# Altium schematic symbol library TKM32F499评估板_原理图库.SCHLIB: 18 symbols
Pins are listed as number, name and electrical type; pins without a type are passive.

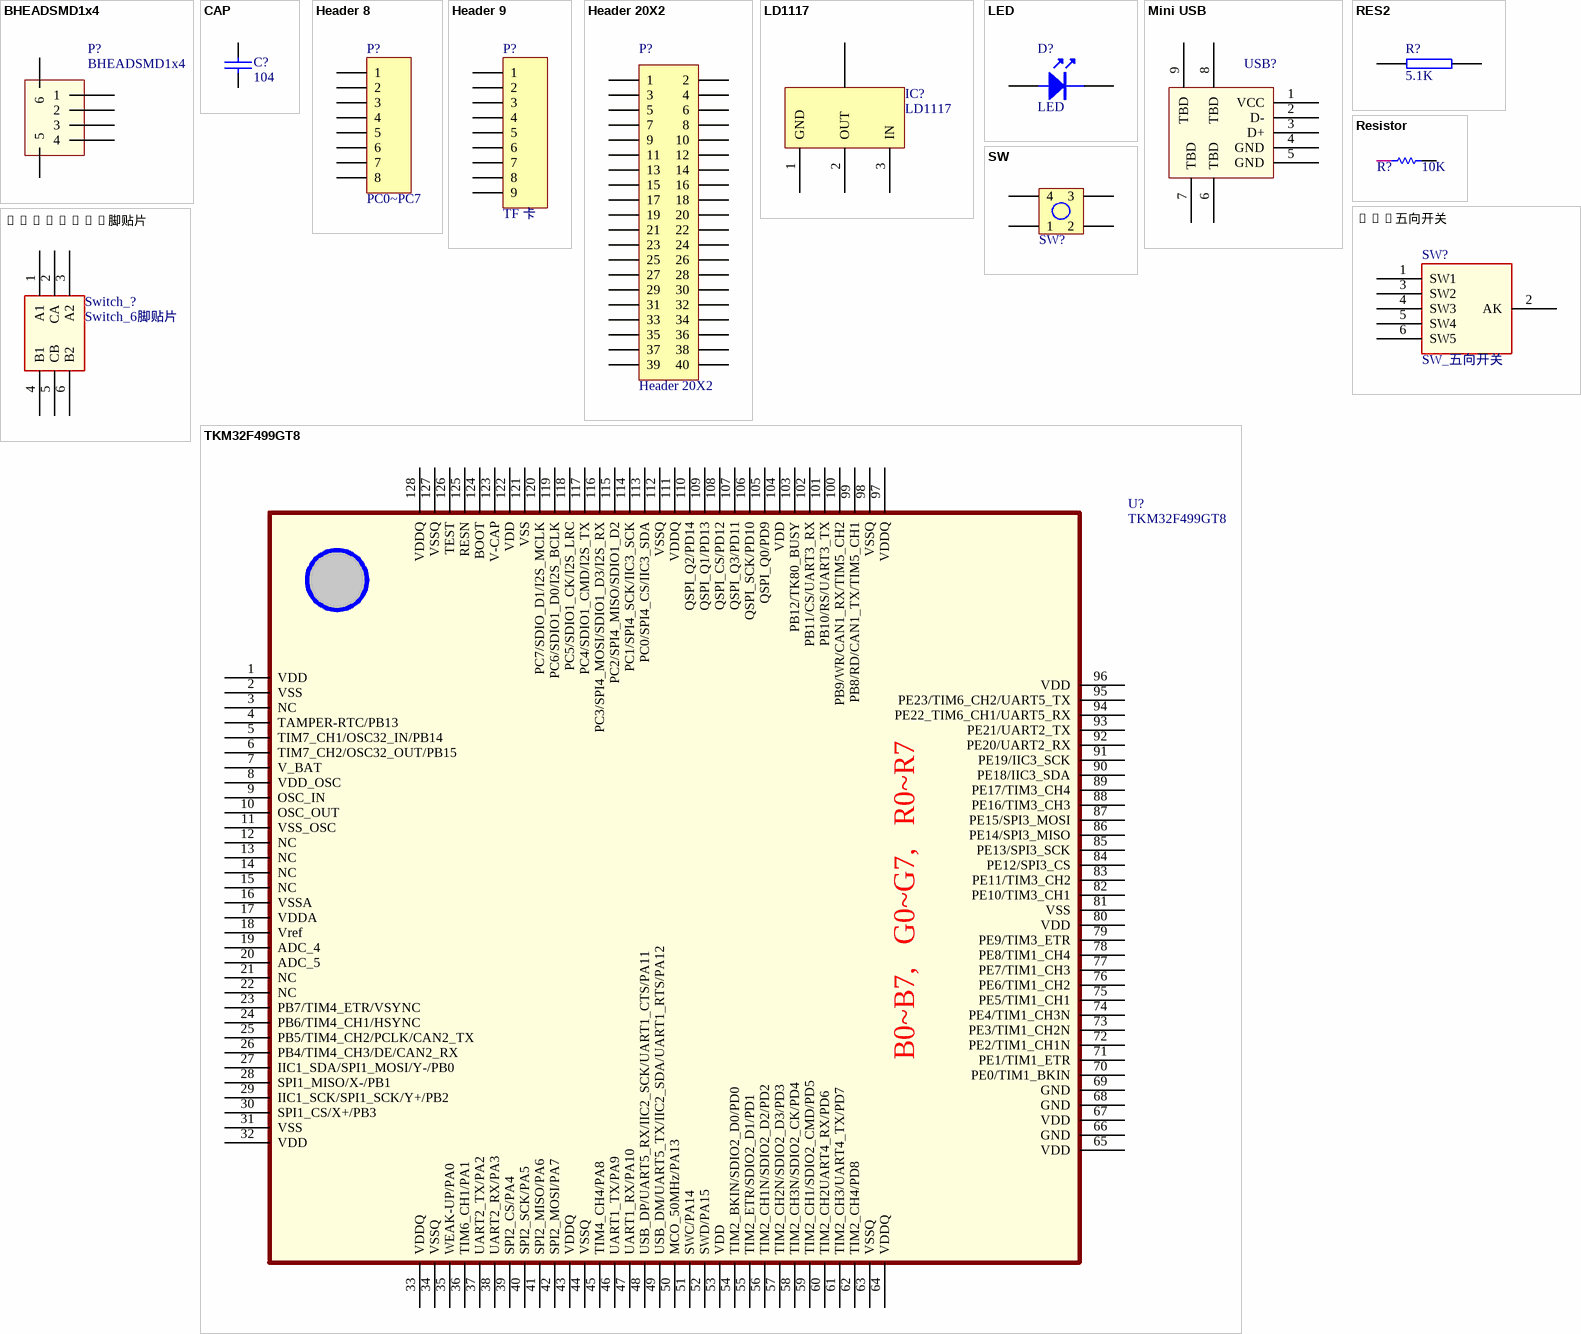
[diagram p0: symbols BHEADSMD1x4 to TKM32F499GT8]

## BHEADSMD1x4
designator P?
footprint BHEADSMD1x4
pins: 1, 2, 3, 4, 5, 6

## CAP
designator C?, comment 104
Capacitor
footprint C0805 (Chip Capacitor; Body 2.0 x 1.2 mm (LxW typ))
footprint R0805
footprint C0603
footprint C0402-1
pins: 1, 2
2 alternate drawings of the same symbol

## Header 8
designator P?, comment PC0~PC7
Header, 8-Pin
footprint HDR1X8 (Connector; Header; 8 Position)
signal-integrity model Connector
pins: 1, 2, 3, 4, 5, 6, 7, 8

## Header 9
designator P?, comment TF 卡
Header, 9-Pin
footprint HDR1X9 (Connector; Header; 9 Position)
signal-integrity model Connector
footprint Micro_SD
pins: 1, 2, 3, 4, 5, 6, 7, 8, 9

## Header 20X2
designator P?
Header, 20-Pin, Dual row
footprint P_Head_2x20
signal-integrity model Connector
pins: 1, 2, 3, 4, 5, 6, 7, 8, 9, 10, 11, 12, 13, 14, 15, 16, 17, 18, 19, 20, 21, 22, 23, 24, 25, 26, 27, 28, 29, 30, 31, 32, 33, 34, 35, 36, 37, 38, 39, 40

## LD1117
designator IC?
footprint SOT223
pins: 1 GND, 2 OUT, 2 OUT, 3 IN

## LED
designator D?
footprint D1206
footprint D0603
pins: 1, 2
2 alternate drawings of the same symbol

## Mini USB
designator USB?, comment Micro USB  (value not drawn)
footprint MicroUSB_带定位柱
pins: 1 VCC, 2 D-, 3 D+, 4 GND, 5 GND, 6 TBD, 7 TBD, 8 TBD, 9 TBD

## RES2
designator R?, comment 5.1K
footprint 0805
footprint R0805
footprint R0402
pins: 1, 2
2 alternate drawings of the same symbol

## Resistor
designator R?, comment 10K
footprint R0402
pins: 1, 2

## SW
designator SW?  (value not drawn)
footprint SW
pins: 1, 2, 3, 4

## SW_五向开关
designator SW?
footprint 五向开关
pins: 1 SW1, 2 AK, 3 SW2, 4 SW3, 5 SW4, 6 SW5

## Switch_6脚贴片
designator Switch_?
footprint Switch_6脚贴片
pins: 1 A1, 2 CA, 3 A2, 4 B1, 5 CB, 6 B2

## TKM32F499GT8
designator U?
footprint LQFP128
pins: 1 VDD, 2 VSS, 3 NC, 4 TAMPER-RTC/PB13, 5 TIM7_CH1/OSC32_IN/PB14, 6 TIM7_CH2/OSC32_OUT/PB15, 7 V_BAT, 8 VDD_OSC, 9 OSC_IN, 10 OSC_OUT, 11 VSS_OSC, 12 NC, 13 NC, 14 NC, 15 NC, 16 VSSA, 17 VDDA, 18 Vref, 19 ADC_4, 20 ADC_5, 21 NC, 22 NC, 23 PB7/TIM4_ETR/VSYNC, 24 PB6/TIM4_CH1/HSYNC, 25 PB5/TIM4_CH2/PCLK/CAN2_TX, 26 PB4/TIM4_CH3/DE/CAN2_RX, 27 IIC1_SDA/SPI1_MOSI/Y-/PB0, 28 SPI1_MISO/X-/PB1, 29 IIC1_SCK/SPI1_SCK/Y+/PB2, 30 SPI1_CS/X+/PB3, 31 VSS, 32 VDD, 33 VDDQ, 34 VSSQ, 35 WEAK-UP/PA0, 36 TIM6_CH1/PA1, 37 UART2_TX/PA2, 38 UART2_RX/PA3, 39 SPI2_CS/PA4, 40 SPI2_SCK/PA5, 41 SPI2_MISO/PA6, 42 SPI2_MOSI/PA7, 43 VDDQ, 44 VSSQ, 45 TIM4_CH4/PA8, 46 UART1_TX/PA9, 47 UART1_RX/PA10, 48 USB_DP/UART5_RX/IIC2_SCK/UART1_CTS/PA11, 49 USB_DM/UART5_TX/IIC2_SDA/UART1_RTS/PA12, 50 MCO_50MHz/PA13, 51 SWC/PA14, 52 SWD/PA15, 53 VDD, 54 TIM2_BKIN/SDIO2_D0/PD0, 55 TIM2_ETR/SDIO2_D1/PD1, 56 TIM2_CH1N/SDIO2_D2/PD2, 57 TIM2_CH2N/SDIO2_D3/PD3, 58 TIM2_CH3N/SDIO2_CK/PD4, 59 TIM2_CH1/SDIO2_CMD/PD5, 60 TIM2_CH2UART4_RX/PD6, 61 TIM2_CH3/UART4_TX/PD7, 62 TIM2_CH4/PD8, 63 VSSQ, 64 VDDQ, 65 VDD, 66 GND, 67 VDD, 68 GND, 69 GND, 70 PE0/TIM1_BKIN, 71 PE1/TIM1_ETR, 72 PE2/TIM1_CH1N, 73 PE3/TIM1_CH2N, 74 PE4/TIM1_CH3N, 75 PE5/TIM1_CH1, 76 PE6/TIM1_CH2, 77 PE7/TIM1_CH3, 78 PE8/TIM1_CH4, 79 PE9/TIM3_ETR, 80 VDD, 81 VSS, 82 PE10/TIM3_CH1, 83 PE11/TIM3_CH2, 84 PE12/SPI3_CS, 85 PE13/SPI3_SCK, 86 PE14/SPI3_MISO, 87 PE15/SPI3_MOSI, 88 PE16/TIM3_CH3, 89 PE17/TIM3_CH4, 90 PE18/IIC3_SDA, 91 PE19/IIC3_SCK, 92 PE20/UART2_RX, 93 PE21/UART2_TX, 94 PE22_TIM6_CH1/UART5_RX, 95 PE23/TIM6_CH2/UART5_TX, 96 VDD, 97 VDDQ, 98 VSSQ, 99 PB8/RD/CAN1_TX/TIM5_CH1, 100 PB9/WR/CAN1_RX/TIM5_CH2, 101 PB10/RS/UART3_TX, 102 PB11/CS/UART3_RX, 103 PB12/TK80_BUSY, 104 VDD, 105 QSPI_Q0/PD9, 106 QSPI_SCK/PD10, 107 QSPI_Q3/PD11, 108 QSPI_CS/PD12, 109 QSPI_Q1/PD13, 110 QSPI_Q2/PD14, 111 VDDQ, 112 VSSQ, 113 PC0/SPI4_CS/IIC3_SDA, 114 PC1/SPI4_SCK/IIC3_SCK, 115 PC2/SPI4_MISO/SDIO1_D2, 116 PC3/SPI4_MOSI/SDIO1_D3/I2S_RX, 117 PC4/SDIO1_CMD/I2S_TX, 118 PC5/SDIO1_CK/I2S_LRC, 119 PC6/SDIO1_D0/I2S_BCLK, 120 PC7/SDIO_D1/I2S_MCLK, 121 VSS, 122 VDD, 123 V-CAP, 124 BOOT, 125 RESN, 126 TEST, 127 VSSQ, 128 VDDQ

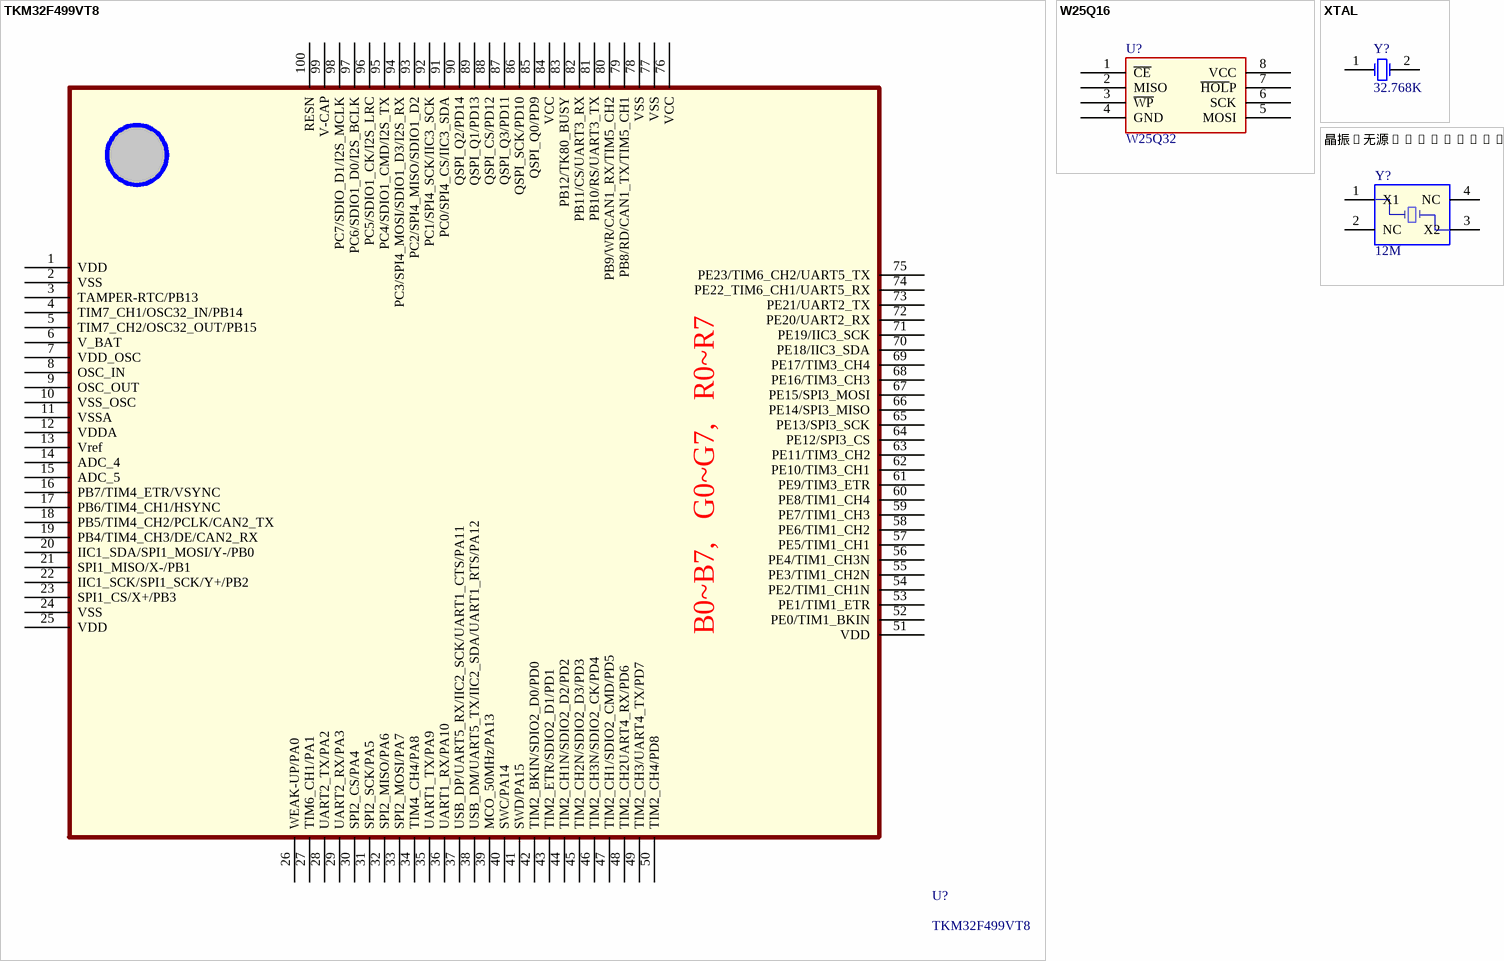
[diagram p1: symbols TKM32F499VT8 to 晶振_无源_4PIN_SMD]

## TKM32F499VT8
designator U?
footprint TQFP100
pins: 1 VDD, 2 VSS, 3 TAMPER-RTC/PB13, 4 TIM7_CH1/OSC32_IN/PB14, 5 TIM7_CH2/OSC32_OUT/PB15, 6 V_BAT, 7 VDD_OSC, 8 OSC_IN, 9 OSC_OUT, 10 VSS_OSC, 11 VSSA, 12 VDDA, 13 Vref, 14 ADC_4, 15 ADC_5, 16 PB7/TIM4_ETR/VSYNC, 17 PB6/TIM4_CH1/HSYNC, 18 PB5/TIM4_CH2/PCLK/CAN2_TX, 19 PB4/TIM4_CH3/DE/CAN2_RX, 20 IIC1_SDA/SPI1_MOSI/Y-/PB0, 21 SPI1_MISO/X-/PB1, 22 IIC1_SCK/SPI1_SCK/Y+/PB2, 23 SPI1_CS/X+/PB3, 24 VSS, 25 VDD, 26 WEAK-UP/PA0, 27 TIM6_CH1/PA1, 28 UART2_TX/PA2, 29 UART2_RX/PA3, 30 SPI2_CS/PA4, 31 SPI2_SCK/PA5, 32 SPI2_MISO/PA6, 33 SPI2_MOSI/PA7, 34 TIM4_CH4/PA8, 35 UART1_TX/PA9, 36 UART1_RX/PA10, 37 USB_DP/UART5_RX/IIC2_SCK/UART1_CTS/PA11, 38 USB_DM/UART5_TX/IIC2_SDA/UART1_RTS/PA12, 39 MCO_50MHz/PA13, 40 SWC/PA14, 41 SWD/PA15, 42 TIM2_BKIN/SDIO2_D0/PD0, 43 TIM2_ETR/SDIO2_D1/PD1, 44 TIM2_CH1N/SDIO2_D2/PD2, 45 TIM2_CH2N/SDIO2_D3/PD3, 46 TIM2_CH3N/SDIO2_CK/PD4, 47 TIM2_CH1/SDIO2_CMD/PD5, 48 TIM2_CH2UART4_RX/PD6, 49 TIM2_CH3/UART4_TX/PD7, 50 TIM2_CH4/PD8, 51 VDD, 52 PE0/TIM1_BKIN, 53 PE1/TIM1_ETR, 54 PE2/TIM1_CH1N, 55 PE3/TIM1_CH2N, 56 PE4/TIM1_CH3N, 57 PE5/TIM1_CH1, 58 PE6/TIM1_CH2, 59 PE7/TIM1_CH3, 60 PE8/TIM1_CH4, 61 PE9/TIM3_ETR, 62 PE10/TIM3_CH1, 63 PE11/TIM3_CH2, 64 PE12/SPI3_CS, 65 PE13/SPI3_SCK, 66 PE14/SPI3_MISO, 67 PE15/SPI3_MOSI, 68 PE16/TIM3_CH3, 69 PE17/TIM3_CH4, 70 PE18/IIC3_SDA, 71 PE19/IIC3_SCK, 72 PE20/UART2_RX, 73 PE21/UART2_TX, 74 PE22_TIM6_CH1/UART5_RX, 75 PE23/TIM6_CH2/UART5_TX, 76 VCC, 77 VSS, 78 VSS, 79 PB8/RD/CAN1_TX/TIM5_CH1, 80 PB9/WR/CAN1_RX/TIM5_CH2, 81 PB10/RS/UART3_TX, 82 PB11/CS/UART3_RX, 83 PB12/TK80_BUSY, 84 VCC, 85 QSPI_Q0/PD9, 86 QSPI_SCK/PD10, 87 QSPI_Q3/PD11, 88 QSPI_CS/PD12, 89 QSPI_Q1/PD13, 90 QSPI_Q2/PD14, 91 PC0/SPI4_CS/IIC3_SDA, 92 PC1/SPI4_SCK/IIC3_SCK, 93 PC2/SPI4_MISO/SDIO1_D2, 94 PC3/SPI4_MOSI/SDIO1_D3/I2S_RX, 95 PC4/SDIO1_CMD/I2S_TX, 96 PC5/SDIO1_CK/I2S_LRC, 97 PC6/SDIO1_D0/I2S_BCLK, 98 PC7/SDIO_D1/I2S_MCLK, 99 V-CAP, 100 RESN

## W25Q16
designator U?, comment W25Q32
footprint SOP8-215-50
pins: 1 ~{CE}, 2 MISO, 3 ~{WP}, 4 GND, 5 MOSI, 6 SCK, 7 ~{HOL}P, 8 VCC

## XTAL
designator Y?, comment 32.768K
Crystal Oscillator
footprint X3215
simulation model XTAL (Spice Subcircuit)
pins: 1 OSC1, 2 OSC2

## 晶振_无源_4PIN_SMD
designator Y?, comment 12M
footprint X3225
footprint X5032
footprint X3225
pins: 1 X1, 2 NC, 3 X2, 4 NC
